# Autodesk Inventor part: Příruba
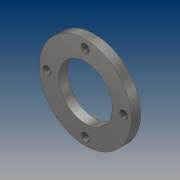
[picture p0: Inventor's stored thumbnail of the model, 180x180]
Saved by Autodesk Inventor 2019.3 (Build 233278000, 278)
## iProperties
Created: 2019-03
Part Number: Příruba
Material: Ocel, legovaná
Document SubType Name: Modeling
Designer: B-hon
Density: 7.73 g/cm^3
Appearance: Pololeštěná
Author: B-hon
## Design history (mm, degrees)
sketch "Náčrt1"
  geometry: C1 r 35 at (0, 0); C2 r 60 at (0, 0); 1 further point
  constraints: 2 centre point, 1 coincident
  dimensions: "d0" = 70 diameter of C1; "d1" = 25 radial gap between concentric circles of C1 C2
extrude "Vysunutí1" new body sketch "Náčrt1" distance "d2" = 12; taper "d3" = 0 deg
sketch "Náčrt2"
  geometry: 2 further points
  dimensions: "d4" = 50 distance of point (0, 0) point (0, 50)
hole "Díra1" sketch "Náčrt2" at (0, 50) diameter "d5" = 10.5; stored, may be unused: countersink angle "d9" = 90 deg, drill point angle "d11" = 118 deg; dims "d6" = 6, "d7" = 4, "d8" = 2, "d10" = 40
pattern_circular "Kruhové pole1" dims angle "d13" = 360 deg
node "Těleso1"
